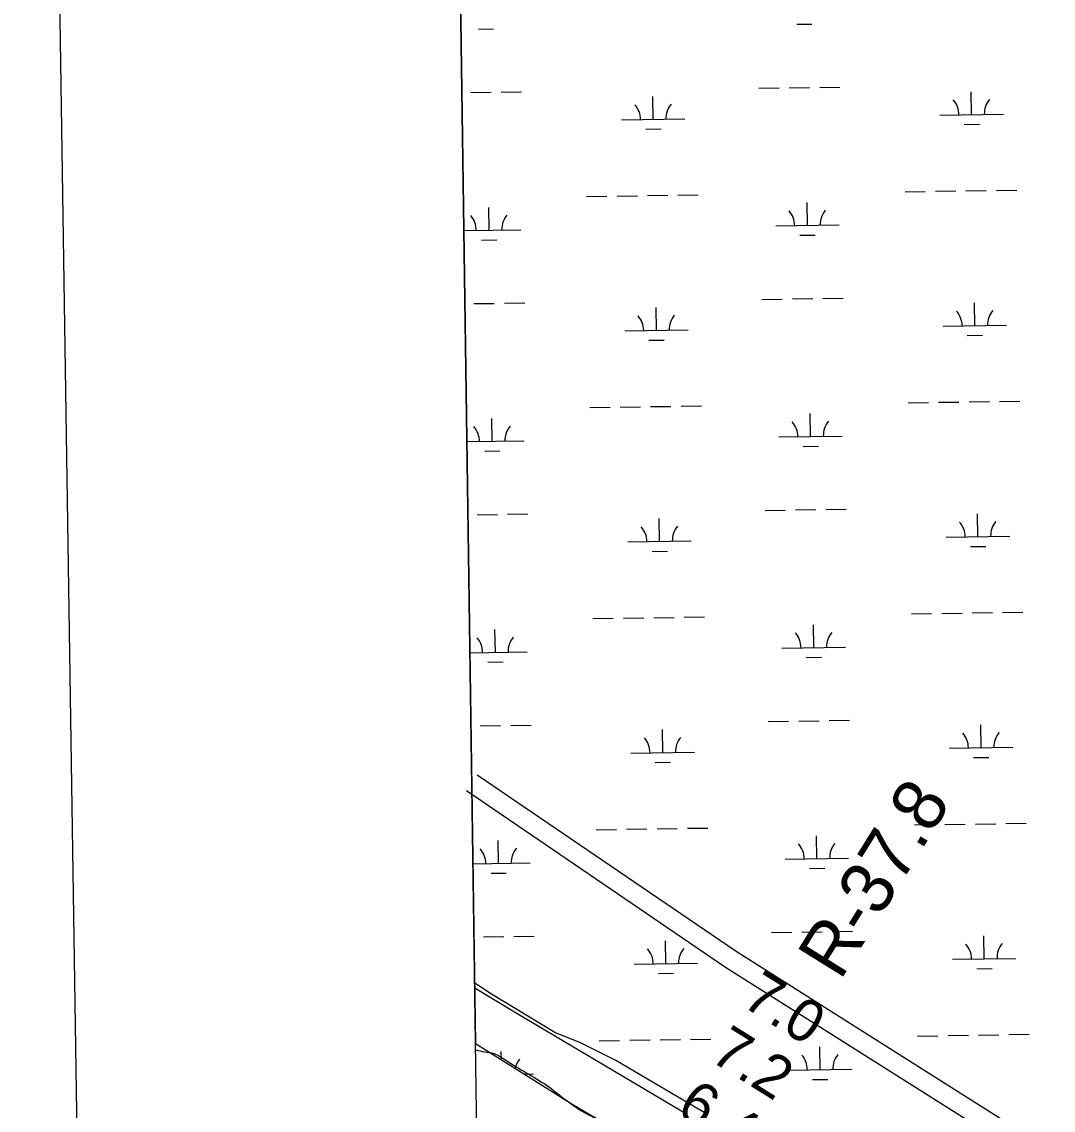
# Model space of a CAD drawing. Extents: x 3807117 to 3845308, y 337856 to 363736.
# Drawn here: x 3810459 to 3812085, y 356278 to 357993 of the extents above; entities that cross this region are included whole.
import ezdxf

# ---------------------------------------------------------------- set-up
doc = ezdxf.new("R2010")
doc.units = 0
for name, color, linetype in [('V-ANNO-SYMB', 7, 'Continuous'), ('V-GRID-FRAM', 7, 'Continuous'), ('V-RIVR-EDGE', 7, 'Continuous'), ('V-RIVR-RANG', 7, 'Continuous'), ('V-RIVR-RANG-IDEN', 7, 'Continuous'), ('V-ROAD-CNTR', 7, 'Continuous'), ('V-SITE-VEGE', 7, 'Continuous'), ('V-TOPO-MINR', 7, 'Continuous'), ('V-WETL-SWMP', 7, 'Continuous')]:
    doc.layers.add(name, color=color, linetype=linetype)

msp = doc.modelspace()

# ---------------------------------------------------------------- linework, layer by layer
at = {"layer": 'V-ANNO-SYMB'}
msp.add_lwpolyline([(3810802.4, 339105.9), (3843881.9, 339601.5), (3843538.6, 362515.5), (3810459.1, 362019.9), (3810802.4, 339105.9)], dxfattribs=at)
at = {"layer": 'V-GRID-FRAM'}
msp.add_lwpolyline([(3811100.6, 361461.9), (3842914.2, 361938.5), (3843194.5, 343758.3), (3811365, 343281.4), (3811100.6, 361461.9)], dxfattribs=at)
at = {"layer": 'V-RIVR-EDGE'}
msp.add_spline([(3811174.6, 356373.1), (3811188.7, 356370), (3811203.6, 356367.3), (3811222.1, 356356.8), (3811286.2, 356317.3), (3811338.6, 356278.8), (3811362.1, 356266.1), (3811376.1, 356260.1), (3811397.3, 356252.4), (3811428.9, 356236.1), (3811458.2, 356216.5), (3811472.2, 356207.9), (3811493.5, 356193.8), (3811502, 356194.7), (3811509.7, 356201), (3811518.8, 356201.5), (3811535.5, 356195.1), (3811546.8, 356183.3), (3811549.5, 356172.5), (3811555.8, 356158.4), (3811561.2, 356151.2), (3811563.9, 356150.7), (3811570.7, 356164.3), (3811577, 356167), (3811587, 356165.6), (3811593.3, 356157.4), (3811593.3, 356147.9), (3811590.5, 356127.6), (3811588.2, 356117.6), (3811588.2, 356110.9), (3811591.8, 356109.5), (3811595.9, 356113.1), (3811603.1, 356121.7), (3811609, 356123), (3811615.4, 356120.3), (3811626.2, 356116.2), (3811633, 356116.2), (3811652.9, 356117.9), (3811659.2, 356118.4), (3811668.7, 356112.9), (3811684.5, 356097.5), (3811704.8, 356068.5), (3811718.7, 356057.6), (3811733.2, 356054.4), (3811778.4, 356035.3), (3811810.9, 356009.5), (3811826.6, 355990.9), (3811837.5, 355972.8), (3811842.9, 355966.4), (3811851, 355959.6), (3811871.8, 355949.2), (3811884.4, 355946), (3811887.6, 355947.3), (3811894.8, 355959.1), (3811900.3, 355966.8), (3811904.4, 355968.1), (3811911.1, 355967.2), (3811933.7, 355960.3), (3811953.6, 355954.9), (3811968.1, 355948), (3811975.3, 355942.2), (3811975.3, 355934), (3811973.9, 355925.4), (3811965.3, 355923.6), (3811954.9, 355917.3), (3811954.4, 355912.8), (3811954.9, 355908.7), (3811959.4, 355907.8), (3811968.9, 355908.3), (3811984.7, 355910.5), (3811997.4, 355911.8), (3812006.4, 355911.3), (3812019.5, 355907.2), (3812036.2, 355901.8), (3812052.5, 355884.5), (3812061, 355876.8), (3812080.4, 355863.7), (3812103.4, 355838.7), (3812123.3, 355824.7), (3812150.9, 355811.5), (3812172.1, 355802.9), (3812200.5, 355791), (3812223.6, 355788.3), (3812292.7, 355755.5), (3812354.5, 355719.7), (3812388.9, 355704.2), (3812435.8, 355683.3), (3812470.2, 355669.6), (3812515.8, 355647.8), (3812561.9, 355627.4), (3812619.7, 355603.3), (3812627.3, 355597.4), (3812632.3, 355581.1), (3812642.2, 355563), (3812652.1, 355554.3), (3812664.7, 355545.3), (3812680.1, 355537.5), (3812689.6, 355537.5), (3812696.4, 355540.2), (3812708.6, 355557.4), (3812712.3, 355559.2), (3812718.6, 355558.7), (3812726.3, 355555.1), (3812727.2, 355547.8), (3812725.3, 355538.3), (3812726.2, 355531.1), (3812730.7, 355527.9), (3812741.6, 355524.7), (3812757.4, 355524.7), (3812770.1, 355528.7), (3812783.2, 355531), (3812801.3, 355531.4), (3812813.9, 355528.6), (3812818, 355524.1), (3812815.2, 355510.5), (3812814.8, 355503.3), (3812822, 355495.1), (3812833.7, 355491), (3812849.5, 355489.2), (3812854.5, 355488.7), (3812866.3, 355482.4), (3812885.7, 355473.3), (3812897.9, 355471), (3812923.2, 355457.8), (3812956.1, 355437.8), (3812980.5, 355421.9), (3813004, 355411.5), (3813028.8, 355399.2), (3813057.7, 355387.4), (3813082.6, 355380.1), (3813107, 355369.2), (3813115.1, 355361.9), (3813141.7, 355342.9), (3813152.5, 355328.4), (3813174.2, 355306.2), (3813192.7, 355289.8), (3813202.6, 355284.8), (3813208.5, 355285.3), (3813218, 355288), (3813230.7, 355292.9), (3813236.6, 355293.4), (3813245.1, 355289.7), (3813263.2, 355285.6), (3813267.7, 355285.1), (3813270, 355286.9), (3813270.5, 355301), (3813271.8, 355301.9), (3813276.8, 355300), (3813295.3, 355295.5), (3813313.4, 355290), (3813325.6, 355285.9), (3813339.2, 355274.6), (3813349.1, 355266.4), (3813373.5, 355254.1), (3813384.3, 355240.1), (3813390.1, 355227.4), (3813401.4, 355221.1), (3813410, 355220.1), (3813420.9, 355220.1), (3813425.4, 355215.6), (3813431.7, 355214.6), (3813438, 355215.1), (3813453, 355219.6), (3813462.9, 355219.5), (3813469.7, 355219.5), (3813510.8, 355200.9), (3813544.2, 355185.9), (3813556.4, 355177.7), (3813570.4, 355157.8), (3813577.6, 355151), (3813584.8, 355149.2), (3813595.7, 355149.6), (3813613.3, 355148.6), (3813625.5, 355148.6), (3813631.4, 355146.8), (3813632.7, 355144.1), (3813630, 355137.3), (3813633.2, 355133.7), (3813638.6, 355130.9), (3813640.8, 355124.1), (3813644.4, 355110.1), (3813651.6, 355103.3), (3813660.2, 355098.8), (3813674.7, 355096.9), (3813690.5, 355097.3), (3813700.9, 355096), (3813718.5, 355087.8), (3813718.5, 355082.4), (3813718.5, 355076), (3813722.5, 355072.9), (3813726.6, 355072.4), (3813733.4, 355078.7), (3813743.4, 355079.6), (3813752.4, 355079.6), (3813764.1, 355077.3), (3813775.4, 355072.3), (3813796.2, 355060.9), (3813812.9, 355052.3), (3813831, 355047.3), (3813835.5, 355047.3), (3813838.7, 355050.9), (3813845.5, 355051.8), (3813851.8, 355051.7), (3813864.5, 355049), (3813875.3, 355044), (3813890.7, 355036.3), (3813893.8, 355028.6), (3813896.5, 355015), (3813904.6, 355000.1), (3813910.4, 354995.5), (3813917.7, 354994.6), (3813923.6, 354996.4), (3813934.4, 355000.9), (3813943.9, 355000.9), (3813953.9, 354998.6), (3813958.8, 354990.9), (3813962.8, 354974.1), (3813969.6, 354969.6), (3813977.7, 354966), (3813995.8, 354961.9), (3814011.6, 354955.5), (3814029.3, 354950), (3814041.9, 354949.5), (3814070.9, 354953.5), (3814078.5, 354955.3), (3814093.5, 354953), (3814098.4, 354946.7), (3814098.8, 354934.5), (3814107.4, 354925), (3814114.6, 354922.7), (3814119.6, 354917.2), (3814117.8, 354903.2), (3814122.7, 354900.9), (3814126.8, 354900.9), (3814133.1, 354905.9), (3814137.7, 354908.1), (3814144.4, 354908.1), (3814158, 354902.7), (3814167.9, 354897.7), (3814183.7, 354889), (3814191.9, 354890.8), (3814207.3, 354894.9), (3814221.7, 354895.7), (3814233.5, 354890.7), (3814249.7, 354878), (3814256, 354862.2), (3814260.5, 354852.7), (3814273.6, 354845.9), (3814287.2, 354843.6), (3814299.8, 354843.5), (3814310.2, 354847.6), (3814334.2, 354848), (3814350.9, 354846.6), (3814373.5, 354840.6), (3814395.2, 354836.1), (3814414.6, 354829.7), (3814430, 354822.4), (3814448, 354805.6), (3814462.5, 354786.2), (3814479.6, 354775.7), (3814501.8, 354768.4), (3814528.4, 354754.3), (3814552.3, 354741.2), (3814565.4, 354730.3), (3814585.3, 354707.2), (3814597.9, 354689.5), (3814607.3, 354680.9), (3814616.4, 354674.6), (3814619.1, 354666.9), (3814617.2, 354657.4), (3814585.5, 354628.1), (3814583.2, 354619.9), (3814583.2, 354612.2), (3814590, 354602.3), (3814597.2, 354600.9), (3814603.5, 354601.3), (3814618, 354609.4), (3814627.5, 354613.9), (3814642, 354622.5), (3814658.3, 354631), (3814666.5, 354643.2), (3814680.1, 354662.2), (3814689.2, 354670.8), (3814695.5, 354672.5), (3814706.4, 354672.5), (3814718.6, 354671.6), (3814729.4, 354671.6), (3814744.3, 354669.3), (3814755.2, 354664.7), (3814764.2, 354652), (3814771.4, 354646.1), (3814784, 354641.6), (3814807.1, 354628), (3814826, 354619.8), (3814850.4, 354609.8), (3814882, 354591.6), (3814905.5, 354574.4), (3814916.8, 354561.2), (3814924.5, 354556.7), (3814939.4, 354556.2), (3814948.9, 354563), (3814953, 354567.5), (3814957, 354567.5), (3814966.1, 354557.9), (3814980.1, 354549.8), (3814987.7, 354549.7), (3814995.4, 354550.2), (3815006.7, 354552.9), (3815016.2, 354552.8), (3815022.1, 354551.5), (3815030.7, 354542.4), (3815042.9, 354538.8), (3815050.6, 354537.8), (3815065.5, 354531), (3815078.6, 354525.1), (3815103, 354515.1), (3815138.6, 354503.2), (3815160.8, 354496.4), (3815178.4, 354486.9), (3815184.7, 354486.9), (3815199.7, 354490), (3815209.2, 354489.5), (3815214.6, 354486.3), (3815223.1, 354477.7), (3815225.4, 354472.7), (3815220.8, 354463.7), (3815221.3, 354456.9), (3815225.3, 354451), (3815233.5, 354451), (3815240.7, 354457.3), (3815243, 354465), (3815248.4, 354469.1), (3815256.1, 354470.9), (3815267.9, 354470.4), (3815274.7, 354467.6), (3815278.7, 354467.6), (3815285.5, 354469), (3815295, 354469.9), (3815300.4, 354464.9), (3815300.9, 354455.4), (3815302.6, 354445.9), (3815313, 354440), (3815324.3, 354437.2), (3815330.2, 354436.8), (3815338.8, 354430.9), (3815351, 354418.6), (3815355.9, 354412.3), (3815365.9, 354409.1), (3815372.2, 354409.1), (3815382.1, 354402.3), (3815391.6, 354398.2), (3815392.5, 354396.4), (3815404.7, 354395.9), (3815419.2, 354395.8), (3815436.8, 354389.5), (3815445.4, 354379.5), (3815457.5, 354368.2), (3815473.8, 354360.4), (3815487.8, 354360.4), (3815509.1, 354365.8), (3815515.4, 354368), (3815523.1, 354373.4), (3815534.4, 354377.5), (3815545.7, 354377.4), (3815556.1, 354371.1), (3815567.4, 354358.4), (3815574.6, 354351.1), (3815578.7, 354351.1), (3815582.3, 354352), (3815589.5, 354353.4), (3815597.7, 354355.2), (3815605.4, 354352.9), (3815608, 354342), (3815617.5, 354323.9), (3815625.2, 354318.5), (3815645.9, 354311.6), (3815662.7, 354310.2), (3815681.7, 354308.4), (3815700.6, 354302.9)], degree=3, dxfattribs=at)
at = {"layer": 'V-ROAD-CNTR'}
for points in [[(3811176.9, 356806.7), (3811585.1, 356528.6), (3812098.3, 356204.2), (3813162.1, 355630.4), (3813949.6, 355328.5), (3815071.1, 354906.2), (3816218.6, 354476.7), (3817272.6, 354151.7), (3817573.4, 354062.4), (3818142.2, 353962.7), (3818819.8, 353880), (3819675, 353862.3)], [(3811160, 356781.9), (3811568.6, 356503.5), (3812083.1, 356178.2), (3813149.6, 355603.1), (3813938.9, 355300.5), (3815060.5, 354878.1), (3816208.9, 354448.3), (3817263.9, 354123), (3817566.5, 354033.2), (3818137.8, 353933.1), (3818817.6, 353850.1), (3819674.9, 353832.3)]]:
    msp.add_lwpolyline(points, dxfattribs=at)
at = {"layer": 'V-SITE-VEGE'}
for p, q in [((3811173.1, 356478.3), (3811129.7, 359458.2)), ((3811199.6, 356461), (3811173.1, 356478.3)), ((3811299.6, 356400.6), (3811199.6, 356461)), ((3811339.6, 356384.4), (3811299.6, 356400.6)), ((3811395.6, 356356.2), (3811339.6, 356384.4)), ((3811519.5, 356283.6), (3811395.6, 356356.2)), ((3811539.5, 356271.6), (3811519.5, 356283.6))]:
    msp.add_line(p, q, dxfattribs=at)
at = {"layer": 'V-TOPO-MINR'}
msp.add_lwpolyline([(3811500.5, 356275.4), (3811238.6, 356431), (3811174.7, 356469.2), (3811173.2, 356470.1)], dxfattribs=at)
at = {"layer": 'V-WETL-SWMP'}
for p, q in [((3811100.6, 361461.9), (3811174.4, 356383.4)), ((3811680.7, 357989.5), (3811704.7, 357989.9)), ((3811178.9, 357982), (3811202.9, 357982.4)), ((3811167, 357881.8), (3811199, 357882.3)), ((3811215, 357882.6), (3811247, 357883)), ((3811620.8, 357888.6), (3811652.8, 357889.1)), ((3811668.8, 357889.4), (3811700.8, 357889.8)), ((3811716.8, 357890.1), (3811748.8, 357890.6)), ((3811956.3, 357847.2), (3811955.8, 357883.2)), ((3811454.5, 357839.7), (3811453.9, 357875.7)), ((3811906.3, 357846.5), (3812006.3, 357848)), ((3811404.5, 357839), (3811504.5, 357840.5)), ((3811944.6, 357831.6), (3811968.5, 357832)), ((3811442.7, 357824.1), (3811466.7, 357824.5)), ((3811851.3, 357725.6), (3811883.3, 357726)), ((3811899.3, 357726.3), (3811931.3, 357726.8)), ((3811947.3, 357727), (3811979.3, 357727.5)), ((3811995.3, 357727.7), (3812027.3, 357728.2)), ((3811349.4, 357718.1), (3811381.4, 357718.5)), ((3811397.4, 357718.8), (3811429.4, 357719.2)), ((3811445.4, 357719.5), (3811477.4, 357720)), ((3811493.4, 357720.2), (3811525.4, 357720.7)), ((3811195.6, 357665), (3811195.1, 357701)), ((3811697.5, 357672.5), (3811696.9, 357708.5)), ((3811155.8, 357664.4), (3811245.6, 357665.7)), ((3811647.5, 357671.8), (3811747.5, 357673.3)), ((3811685.7, 357656.9), (3811709.7, 357657.3)), ((3811183.9, 357649.4), (3811207.9, 357649.7)), ((3811625.8, 357556), (3811657.8, 357556.5)), ((3811673.8, 357556.7), (3811705.8, 357557.2)), ((3811721.8, 357557.4), (3811753.8, 357557.9)), ((3811171.9, 357549.2), (3811203.9, 357549.7)), ((3811219.9, 357549.9), (3811251.9, 357550.4)), ((3811459.5, 357507.1), (3811458.9, 357543.1)), ((3811961.3, 357514.6), (3811960.8, 357550.6)), ((3811409.5, 357506.3), (3811509.4, 357507.8)), ((3811911.3, 357513.8), (3812011.3, 357515.3)), ((3811447.7, 357491.5), (3811471.7, 357491.8)), ((3811949.5, 357499), (3811973.5, 357499.3)), ((3811354.4, 357385.4), (3811386.4, 357385.9)), ((3811402.4, 357386.1), (3811434.4, 357386.6)), ((3811450.4, 357386.9), (3811482.4, 357387.3)), ((3811498.4, 357387.6), (3811530.4, 357388)), ((3811856.3, 357392.9), (3811888.3, 357393.4)), ((3811904.3, 357393.7), (3811936.3, 357394.1)), ((3811952.3, 357394.4), (3811984.3, 357394.8)), ((3812000.3, 357395.1), (3812032.3, 357395.6)), ((3811200.6, 357332.4), (3811200.1, 357368.4)), ((3811702.5, 357339.9), (3811701.9, 357375.9)), ((3811160.6, 357331.8), (3811250.6, 357333.1)), ((3811652.5, 357339.1), (3811752.5, 357340.6)), ((3811188.8, 357316.8), (3811212.8, 357317.1)), ((3811690.7, 357324.3), (3811714.7, 357324.6)), ((3811176.9, 357216.6), (3811208.9, 357217)), ((3811224.9, 357217.3), (3811256.9, 357217.8)), ((3811630.8, 357223.4), (3811662.8, 357223.8)), ((3811678.8, 357224.1), (3811710.8, 357224.6)), ((3811726.8, 357224.8), (3811758.8, 357225.3)), ((3811966.3, 357182), (3811965.7, 357217.9)), ((3811464.4, 357174.4), (3811463.9, 357210.4)), ((3811916.3, 357181.2), (3812016.3, 357182.7)), ((3811414.4, 357173.7), (3811514.4, 357175.2)), ((3811954.5, 357166.3), (3811978.5, 357166.7)), ((3811452.7, 357158.8), (3811476.7, 357159.2)), ((3811861.3, 357060.3), (3811893.3, 357060.8)), ((3811909.2, 357061), (3811941.2, 357061.5)), ((3811957.2, 357061.7), (3811989.2, 357062.2)), ((3812005.2, 357062.5), (3812037.2, 357062.9)), ((3811359.4, 357052.8), (3811391.4, 357053.3)), ((3811407.4, 357053.5), (3811439.4, 357054)), ((3811455.4, 357054.2), (3811487.4, 357054.7)), ((3811503.4, 357054.9), (3811535.4, 357055.4)), ((3811707.4, 357007.2), (3811706.9, 357043.2)), ((3811205.6, 356999.7), (3811205, 357035.7)), ((3811657.4, 357006.5), (3811757.4, 357008)), ((3811165.5, 356999.1), (3811255.6, 357000.5)), ((3811695.7, 356991.6), (3811719.7, 356992)), ((3811193.8, 356984.1), (3811217.8, 356984.5)), ((3811229.9, 356884.6), (3811261.9, 356885.1)), ((3811635.8, 356890.7), (3811667.8, 356891.2)), ((3811683.8, 356891.4), (3811715.8, 356891.9)), ((3811731.8, 356892.2), (3811763.8, 356892.6)), ((3811971.3, 356849.3), (3811970.7, 356885.3)), ((3811181.9, 356883.9), (3811213.9, 356884.4)), ((3811469.4, 356841.8), (3811468.9, 356877.8)), ((3811419.4, 356841), (3811519.4, 356842.5)), ((3811921.3, 356848.6), (3812021.3, 356850.1)), ((3811959.5, 356833.7), (3811983.5, 356834.1)), ((3811457.7, 356826.2), (3811481.6, 356826.5)), ((3811364.4, 356720.1), (3811396.4, 356720.6)), ((3811412.4, 356720.9), (3811444.4, 356721.3)), ((3811460.4, 356721.6), (3811492.4, 356722.1)), ((3811508.4, 356722.3), (3811540.4, 356722.8)), ((3811866.2, 356727.7), (3811898.2, 356728.1)), ((3811914.2, 356728.4), (3811946.2, 356728.9)), ((3811962.2, 356729.1), (3811994.2, 356729.6)), ((3812010.2, 356729.8), (3812042.2, 356730.3)), ((3811210.6, 356667.1), (3811210, 356703.1)), ((3811712.4, 356674.6), (3811711.9, 356710.6)), ((3811170.3, 356666.5), (3811260.6, 356667.8)), ((3811662.4, 356673.9), (3811762.4, 356675.4)), ((3811198.8, 356651.5), (3811222.8, 356651.8)), ((3811700.7, 356659), (3811724.7, 356659.4)), ((3811688.7, 356558.8), (3811720.7, 356559.3)), ((3811736.7, 356559.5), (3811768.7, 356560)), ((3811186.9, 356551.3), (3811218.9, 356551.8)), ((3811234.9, 356552), (3811266.9, 356552.5)), ((3811474.4, 356509.2), (3811473.9, 356545.2)), ((3811640.8, 356558.1), (3811672.7, 356558.6)), ((3811976.3, 356516.7), (3811975.7, 356552.7)), ((3811424.4, 356508.4), (3811524.4, 356509.9)), ((3811926.3, 356515.9), (3812026.2, 356517.4)), ((3811462.6, 356493.5), (3811486.6, 356493.9)), ((3811964.5, 356501.1), (3811988.5, 356501.4)), ((3811369.4, 356387.5), (3811401.4, 356388)), ((3811417.4, 356388.2), (3811449.4, 356388.7)), ((3811465.4, 356388.9), (3811497.4, 356389.4)), ((3811513.4, 356389.7), (3811545.4, 356390.1)), ((3811871.2, 356395), (3811903.2, 356395.5)), ((3811919.2, 356395.7), (3811951.2, 356396.2)), ((3811967.2, 356396.5), (3811999.2, 356396.9)), ((3812015.2, 356397.2), (3812047.2, 356397.7)), ((3811174.4, 356383.4), (3811327.8, 356287.2)), ((3811717.4, 356342), (3811716.9, 356378)), ((3811215.2, 356357.8), (3811215, 356370.4)), ((3811667.4, 356341.2), (3811767.4, 356342.7)), ((3811251.6, 356335), (3811265.5, 356335.2)), ((3811705.6, 356326.4), (3811729.6, 356326.7)), ((3811327.8, 356287.2), (3811610.1, 356121.7))]:
    msp.add_line(p, q, dxfattribs=at)
for centre, start, end in [((3811509.7, 357841), 140.0865, 181.6302), ((3811901.1, 357846.9), 0.0865, 41.6302), ((3812011.5, 357848.5), 140.0865, 181.6302), ((3811399.2, 357839.4), 0.0865, 41.6302), ((3811642.2, 357672.2), 0.0865, 41.6302), ((3811752.7, 357673.8), 140.0865, 181.6302), ((3811140.4, 357664.6), 0.0865, 41.6302), ((3811250.9, 357666.3), 140.0865, 181.6302), ((3811906.1, 357514.2), 0.0865, 41.6302), ((3812016.5, 357515.9), 140.0865, 181.6302), ((3811404.2, 357506.7), 0.0865, 41.6302), ((3811514.7, 357508.4), 140.0865, 181.6302), ((3811145.4, 357332), 0.0865, 41.6302), ((3811255.8, 357333.7), 140.0865, 181.6302), ((3811647.2, 357339.5), 0.0865, 41.6302), ((3811757.7, 357341.2), 140.0865, 181.6302), ((3811409.2, 357174.1), 0.0865, 41.6302), ((3811519.7, 357175.7), 140.0865, 181.6302), ((3811911, 357181.6), 0.0865, 41.6302), ((3812021.5, 357183.3), 140.0865, 181.6302), ((3811150.3, 356999.4), 0.0865, 41.6302), ((3811260.8, 357001), 140.0865, 181.6302), ((3811652.2, 357006.9), 0.0865, 41.6302), ((3811762.7, 357008.5), 140.0865, 181.6302), ((3811916, 356849), 0.0865, 41.6302), ((3812026.5, 356850.6), 140.0865, 181.6302), ((3811414.2, 356841.4), 0.0865, 41.6302), ((3811524.6, 356843.1), 140.0865, 181.6302), ((3811657.2, 356674.3), 0.0865, 41.6302), ((3811767.7, 356675.9), 140.0865, 181.6302), ((3811155.3, 356666.7), 0.0865, 41.6302), ((3811265.8, 356668.4), 140.0865, 181.6302), ((3811419.2, 356508.8), 0.0865, 41.6302), ((3811529.6, 356510.5), 140.0865, 181.6302), ((3811921, 356516.3), 0.0865, 41.6302), ((3812031.5, 356518), 140.0865, 181.6302), ((3811270.8, 356335.8), 140.0865, 165.7889), ((3811662.2, 356341.6), 0.0865, 41.6302), ((3811772.6, 356343.3), 140.0865, 181.6302)]:
    msp.add_arc(centre, 35.2, start, end, dxfattribs=at)

# ---------------------------------------------------------------- texts
at = {"layer": 'V-RIVR-RANG'}
for s, p in [('7.0', (3811591.5, 356444.2)), ('7.2', (3811541.2, 356357.8)), ('6.4', (3811488.5, 356272.8))]:
    msp.add_text(s, height=67, rotation=328.0183, dxfattribs=at).set_placement(p)
at = {"layer": 'V-RIVR-RANG-IDEN'}
msp.add_text('R-37.8', height=83, rotation=58.1559, dxfattribs=at).set_placement((3811749.1, 356480.9))

doc.saveas('drawing.dxf')
